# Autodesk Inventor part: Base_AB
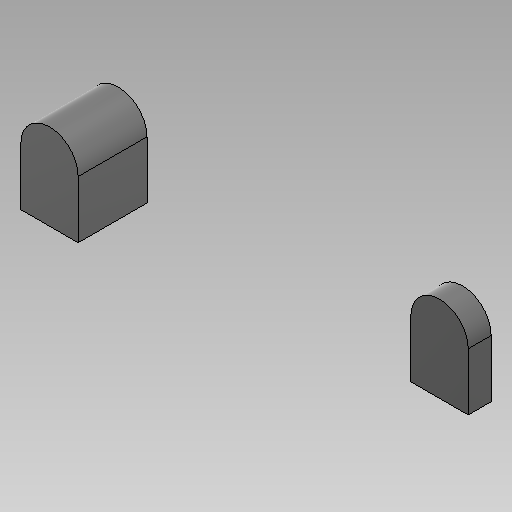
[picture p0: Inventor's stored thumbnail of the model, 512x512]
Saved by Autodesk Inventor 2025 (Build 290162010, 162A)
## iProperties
Created: 2024-10
Part Number: Base_AB
Material: Generic
Document SubType Name: Modeling
Designer: Dennis
Mass: 0.27854 g
Surface Area: 3.22102 cm^2
Volume: 0.27854 cm^3
Density: 1 g/cm^3
Appearance: Smooth - Black
Author: Dennis
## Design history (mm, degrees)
sketch "Sketch1"
  geometry: L1 (-2.5, 0)-(-2.5, -5); L2 (-2.5, -5)-(2.5, -5); L3 (2.5, 0)-(2.5, -5); L4 (27.5, 0)-(27.5, -5); L5 (27.5, -5)-(32.5, -5); L6 (32.5, 0)-(32.5, -5); A1 r 2.5 centre (0, 0) between (2.5, 0) and (-2.5, 0); A2 r 2.5 centre (30, 0) between (32.5, 0) and (27.5, 0); 1 further point
  constraints: 12 end point, 4 point on circle, 4 tangent, 4 vertical, 2 centre point, 2 equal length, 2 perpendicular, 1 coincident, 1 equal radius, 1 horizontal alignment
  dimensions: "d0" = 5 distance between parallel lines of L1 L3 (= w_); "d1" = 30 distance of A1.centre A2.centre (= AB_)
extrude "Extrusion1" new body sketch "Sketch1" stored distance "d2" = 6 (= 3 x t_); taper "d3" = 0 deg
sketch "Sketch2"
  geometry: L1 (27.5, 0)-(27.5, -5) reference; L2 (27.5, -5)-(32.5, -5) reference; L3 (32.5, -5)-(32.5, 0) reference; A1 r 2.5 centre (30, 0) between (32.5, 0) and (27.5, 0) reference; 1 further point
extrude "Extrusion2" cut sketch "Sketch2" distance "d4" = 4 (= 2 x t_); taper "d5" = 0 deg
body "Solid1"
node "Projected Loop1"
other parameters: "AB_" = 30 [user parameter; used in 1 equation term], "w_" = 5 [user parameter; used in 1 equation term], "t_" = 2 [user parameter; used in 2 equation terms]
